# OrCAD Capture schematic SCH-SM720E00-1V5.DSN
size C; title: SM720E00; rev: 1.0; note: <>
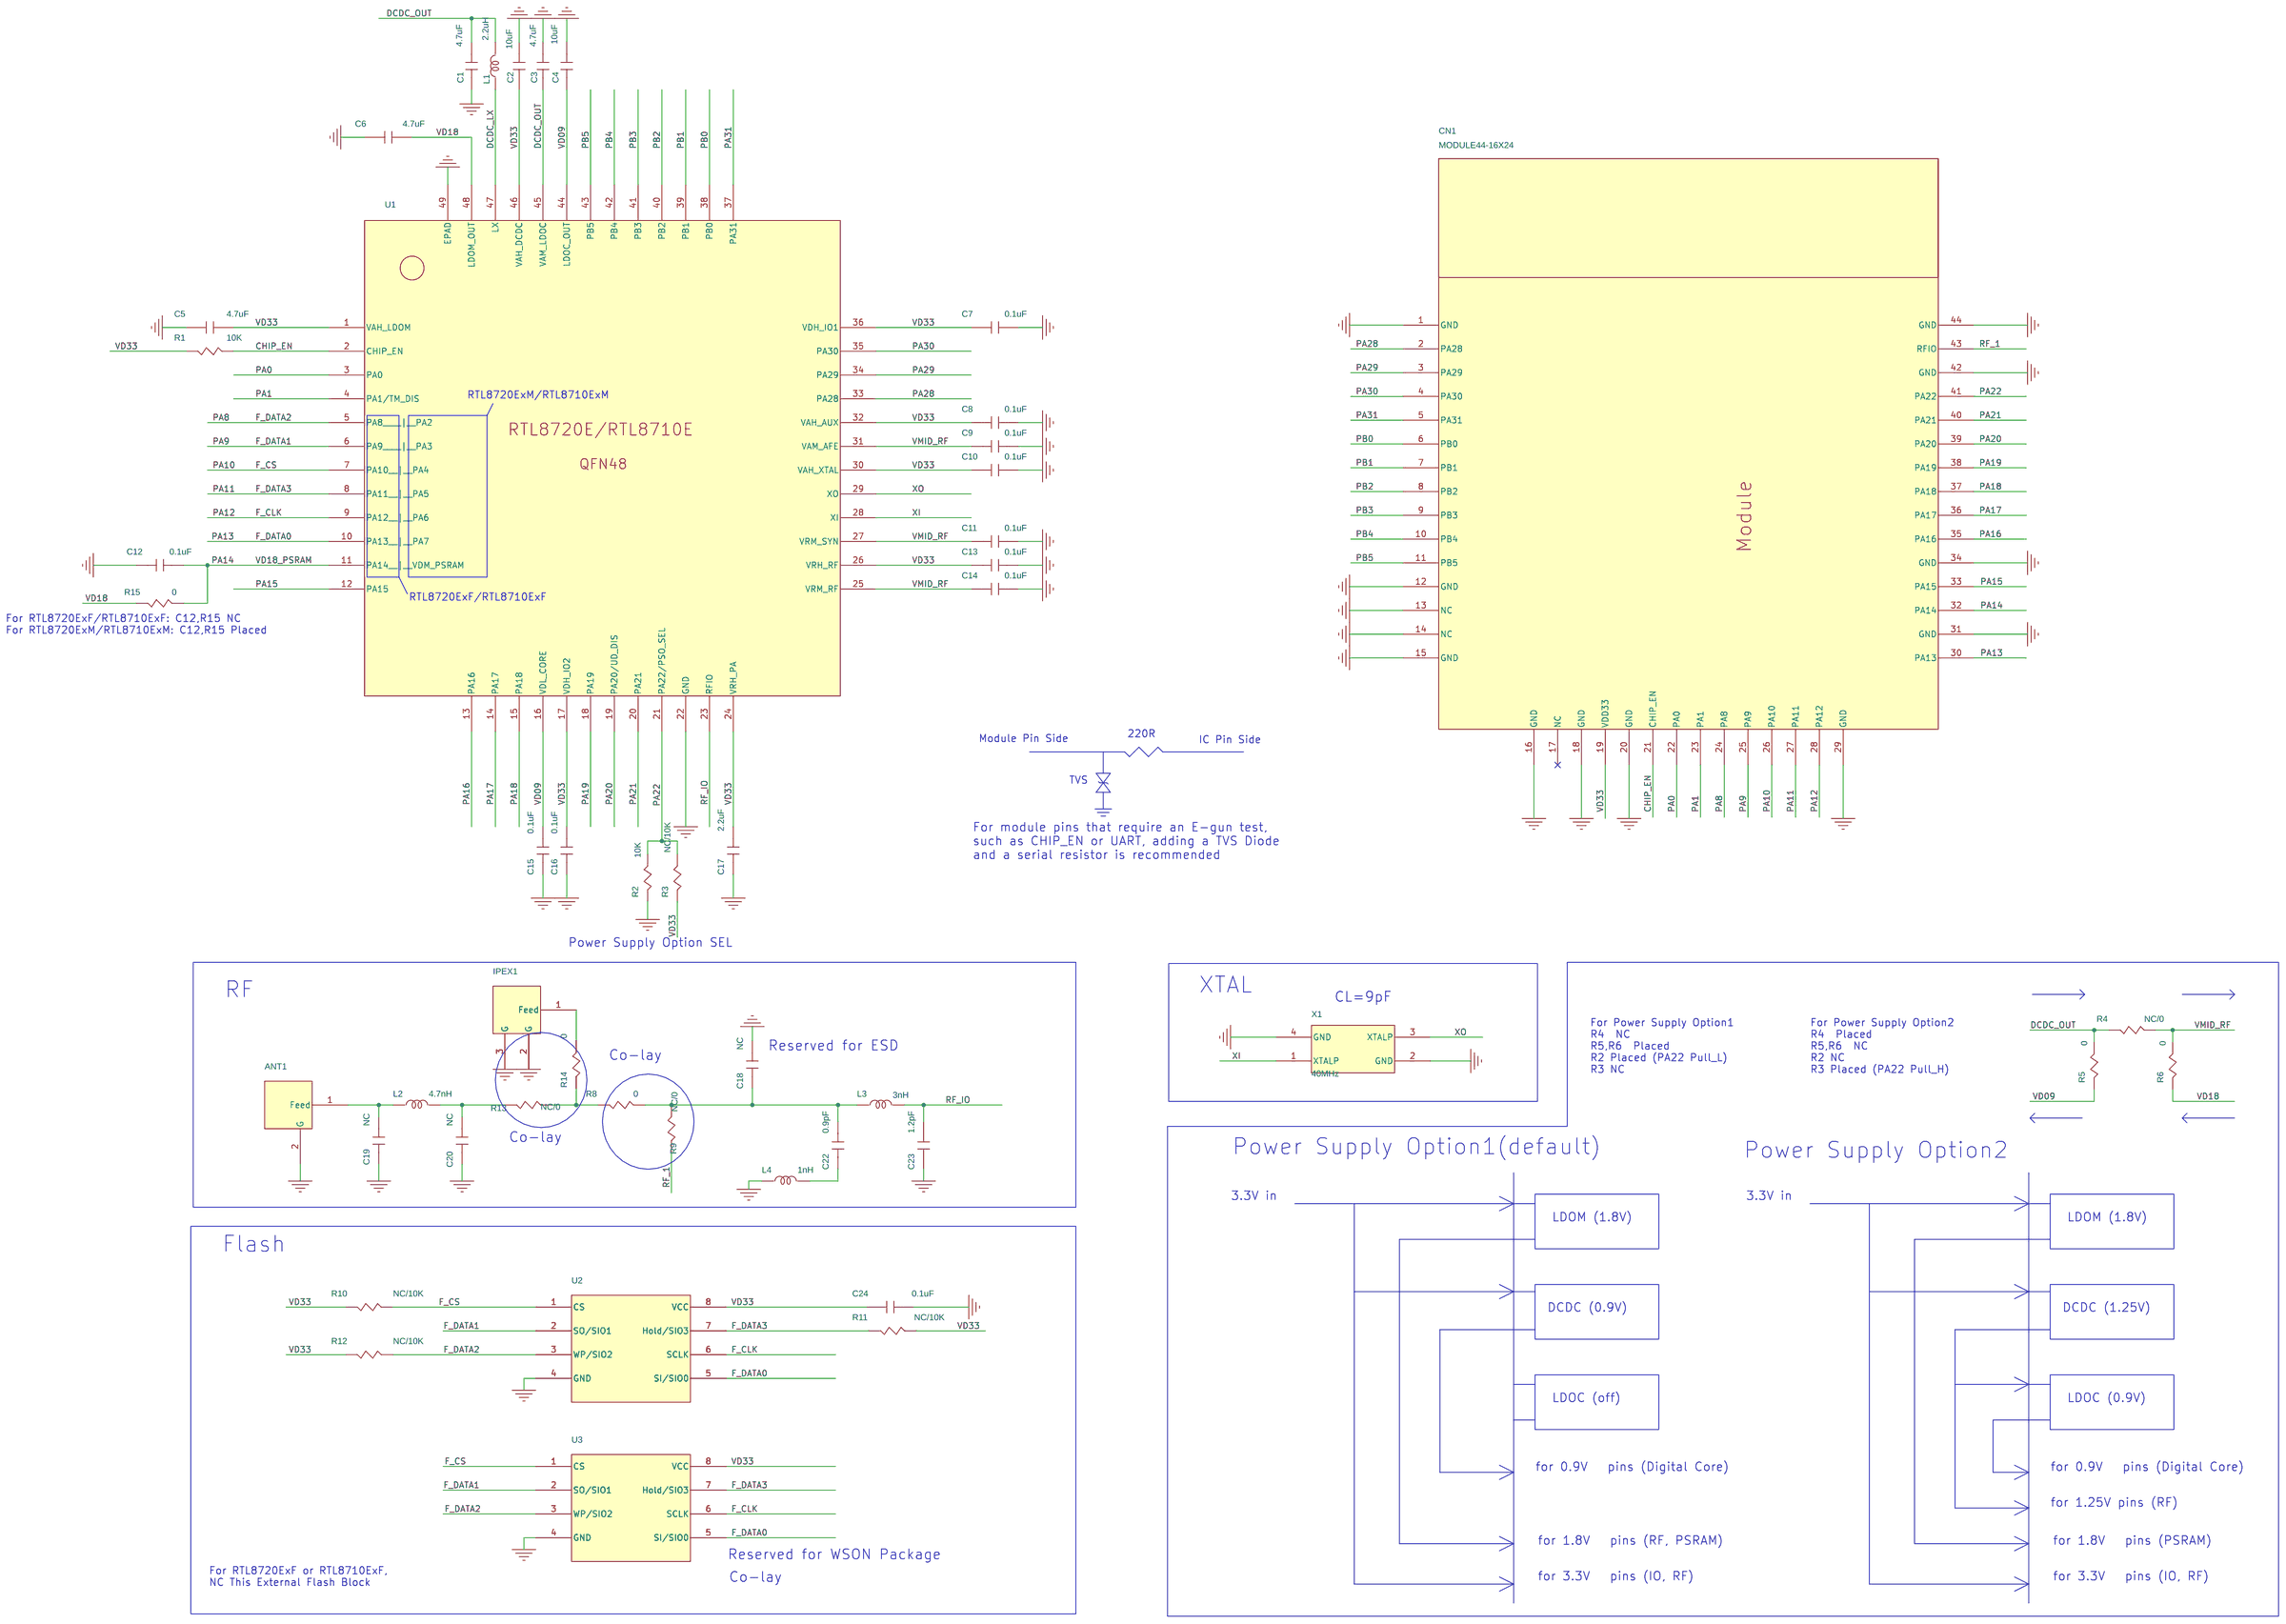
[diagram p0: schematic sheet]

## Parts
ANT1  TP  [LITE_PANT2]
C1  4.7uF  [C0402]
C2  10uF  [C0603]
C3  4.7uF  [C0402]
C4  10uF  [C0603]
C5  4.7uF  [C0402]
C6  4.7uF  [C0402]
C7  0.1uF  [C0201]
C8  0.1uF  [C0201]
C9  0.1uF  [C0201]
C10  0.1uF  [C0201]
C11  0.1uF  [C0201]
C12  0.1uF  [C0201]
C13  0.1uF  [C0201]
C14  0.1uF  [C0201]
C15  0.1uF  [C0201]
C16  0.1uF  [C0201]
C17  2.2uF  [C0402]
C18  NC  [C0201]
C19  NC  [C0201]
C20  NC  [C0201]
C22  0.9pF  [C0201]
C23  1.2pF  [C0201]
C24  0.1uF  [C0201]
CN1  MODULE44-16X24  [MODULE44-16X24]
IPEX1  TP  [IPEX-0.7X2.2-1.35]
L1  2.2uH  [L0805]
L2  4.7nH  [L0201]
L3  3nH  [L0201]
L4  1nH  [L0201]
R1  10K  [R0201]
R2  10K  [R0201]
R3  NC/10K  [R0201]
R4  NC/0  [R0402]
R5  0  [R0402]
R6  0  [R0402]
R8  0  [R0201]
R9  NC/0  [R0201]
R10  NC/10K  [R0201]
R11  NC/10K  [R0201]
R12  NC/10K  [R0201]
R13  NC/0  [R0201]
R14  0  [R0201]
R15  0  [R0201]
U1  RTL8720EAM  [QFN48_6_6]
U2  NC  [SOIC8-1.27-156]
U3  NC  [WSON8-1.27-6X5-RM-EPAD]
X1  40MHz  [XTAL-2016]

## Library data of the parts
ANT1 = TP_2
C1-C20 C22-C24 = C_402
CN1 = R0402_12.06K_WALSIN
IPEX1 = TP_3
L1-L4 = L0402_1.7NH_ACX
R1-R6 R8-R15 = R0402_1.06K_WALSIN
U1 = AmebaLite_QFN48_single_13
U2 U3 = 9346_18
X1 = 9346_0

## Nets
GND: ANT1.2(G) C1.1 C2.1 C3.1 C4.2 C5.1 C6.2 C7.1 C8.1 C9.1 C10.1 C11.1 C12.2 C13.1 C14.1 C15.1 C16.1 C17.1 C18.1 C19.1 C20.1 C23.2 C24.2 CN1.1(GND) CN1.12(GND) CN1.13(NC) CN1.14(NC) CN1.15(GND) CN1.16(GND) CN1.18(GND) CN1.20(GND) CN1.29(GND) CN1.31(GND) CN1.34(GND) CN1.42(GND) CN1.44(GND) IPEX1.2(G) IPEX1.3(G) L4.1 R2.2 U1.22(GND) U1.49(EPAD) U2.4(GND) U3.4(GND) X1.2(GND) X1.4(GND)
CHIP_EN: CN1.21(CHIP_EN) R1.1 U1.2(CHIP_EN)
DCDC_LX: L1.1 U1.47(LX)
DCDC_OUT: C1.2 C3.2 L1.2 R4.2 R5.1 U1.45(VAM_LDOC)
F_CLK: CN1.28(PA12) U1.9(PA12__|__PA6) U2.6(SCLK) U3.6(SCLK)
F_CS: CN1.26(PA10) R10.1 U1.7(PA10__|__PA4) U2.1(CS) U3.1(CS)
F_DATA0: CN1.30(PA13) U1.10(PA13__|__PA7) U2.5(SI/SIO0) U3.5(SI/SIO0)
F_DATA1: CN1.25(PA9) U1.6(PA9____|__PA3) U2.2(SO/SIO1) U3.2(SO/SIO1)
F_DATA2: CN1.24(PA8) R12.1 U1.5(PA8____|__PA2) U2.3(WP/SIO2) U3.3(WP/SIO2)
F_DATA3: CN1.27(PA11) R11.2 U1.8(PA11__|__PA5) U2.7(Hold/SIO3) U3.7(Hold/SIO3)
PA0: CN1.22(PA0) U1.3(PA0)
PA1: CN1.23(PA1) U1.4(PA1/TM_DIS)
PA14: C12.1 CN1.32(PA14) R15.1 U1.11(PA14__|__VDM_PSRAM)
PA15: CN1.33(PA15) U1.12(PA15)
PA16: CN1.35(PA16) U1.13(PA16)
PA17: CN1.36(PA17) U1.14(PA17)
PA18: CN1.37(PA18) U1.15(PA18)
PA19: CN1.38(PA19) U1.18(PA19)
PA20: CN1.39(PA20) U1.19(PA20/UD_DIS)
PA21: CN1.40(PA21) U1.20(PA21)
PA22: CN1.41(PA22) R2.1 R3.1 U1.21(PA22/PSO_SEL)
PA28: CN1.2(PA28) U1.33(PA28)
PA29: CN1.3(PA29) U1.34(PA29)
PA30: CN1.4(PA30) U1.35(PA30)
PA31: CN1.5(PA31) U1.37(PA31)
PB0: CN1.6(PB0) U1.38(PB0)
PB1: CN1.7(PB1) U1.39(PB1)
PB2: CN1.8(PB2) U1.40(PB2)
PB3: CN1.9(PB3) U1.41(PB3)
PB4: CN1.10(PB4) U1.42(PB4)
PB5: CN1.11(PB5) U1.43(PB5)
RF_1: CN1.43(RFIO) R9.2
RF_IO: C23.1 L3.2 U1.23(RFIO)
VD09: C4.1 C15.2 R5.2 U1.16(VDL_CORE) U1.44(LDOC_OUT)
VD18: C6.1 R6.2 R15.2 U1.48(LDOM_OUT)
VD33: C2.2 C5.2 C7.2 C8.2 C10.2 C13.2 C16.2 C17.2 C24.1 CN1.19(VDD33) R1.2 R3.2 R10.2 R11.1 R12.2 U1.1(VAH_LDOM) U1.17(VDH_IO2) U1.24(VRH_PA) U1.26(VRH_RF) U1.30(VAH_XTAL) U1.32(VAH_AUX) U1.36(VDH_IO1) U1.46(VAH_DCDC) U2.8(VCC) U3.8(VCC)
VMID_RF: C9.2 C11.2 C14.2 R4.1 R6.1 U1.25(VRM_RF) U1.27(VRM_SYN) U1.31(VAM_AFE)
XI: U1.28(XI) X1.1(XTALP)
XO: U1.29(XO) X1.3(XTALP)
N05065: C20.2 L2.2 R13.2
N05089: C18.2 C22.1 L3.1 R8.1 R9.1
N05235: C22.2 L4.2
N05434: ANT1.1(Feed) C19.2 L2.1
N16319172: IPEX1.1(Feed) R14.1
N16319276: R8.2 R13.1 R14.2

Not connected (* = marked no-connect by the designer): CN1 17(NC)*

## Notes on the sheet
- RTL8720ExM/RTL8710ExM
- RTL8720ExF/RTL8710ExF
- For RTL8720ExF/RTL8710ExF: C12,R15 NC
  For RTL8720ExM/RTL8710ExM: C12,R15 Placed
- 220R
- Module Pin Side
- IC Pin Side
- TVS
- For module pins that require an E-gun test,
  such as CHIP_EN or UART, adding a TVS Diode
  and a serial resistor is recommended
- Power Supply Option SEL
- RF
- XTAL
- CL=9pF
- For Power Supply Option1
  R4  NC
  R5,R6  Placed
  R2 Placed (PA22 Pull_L)
  R3 NC
- For Power Supply Option2
  R4  Placed
  R5,R6  NC
  R2 NC
  R3 Placed (PA22 Pull_H)
- Reserved for ESD
- Co-lay
- Co-lay
- Power Supply Option1(default)
- Power Supply Option2
- 3.3V in
- 3.3V in
- LDOM (1.8V)
- LDOM (1.8V)
- Flash
- DCDC (0.9V)
- DCDC (1.25V)
- LDOC (off)
- LDOC (0.9V)
- for 0.9V   pins (Digital Core)
- for 0.9V   pins (Digital Core)
- for 1.25V pins (RF)
- for 1.8V   pins (RF, PSRAM)
- for 1.8V   pins (PSRAM)
- Reserved for WSON Package
- For RTL8720ExF or RTL8710ExF,
  NC This External Flash Block
- Co-lay
- for 3.3V   pins (IO, RF)
- for 3.3V   pins (IO, RF)
